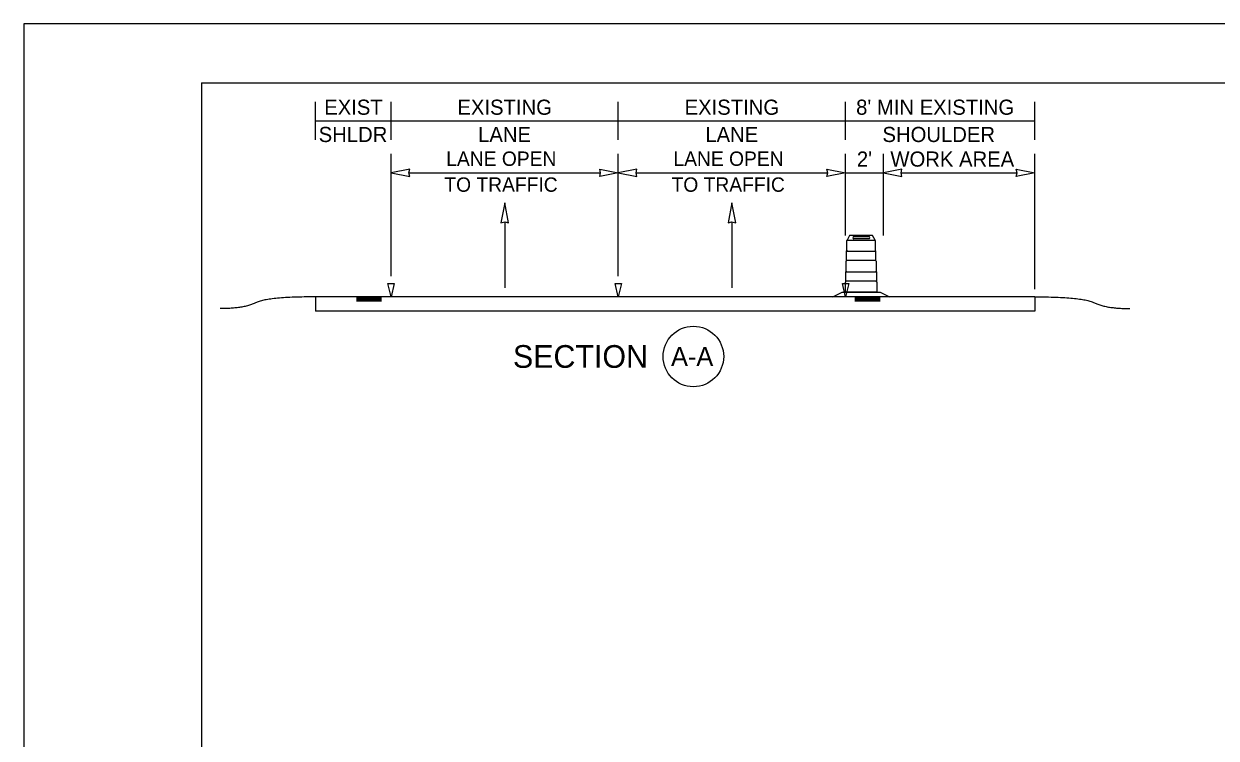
# Model space of a CAD drawing. Extents: x 99999.1 to 100055.7, y 99995 to 100013.2.
# Drawn here: x 99999.06 to 100005.36, y 100006.91 to 100010.69 of the extents above; entities that cross this region are included whole.
import ezdxf

# ---------------------------------------------------------------- set-up
doc = ezdxf.new("R2010")
doc.units = 0
for name, color, linetype in [('SH_GI_PlotLimits', 7, 'Continuous'), ('SH_GI_SheetBorder', 7, 'Continuous'), ('SH_TI_WZSectionCut', 7, 'Continuous'), ('TR_WZ_ArrowLeftStrRightTurn', 7, 'Continuous'), ('TR_WZ_TrafficSafetyDrumElev', 7, 'Continuous')]:
    doc.layers.add(name, color=color, linetype=linetype)

msp = doc.modelspace()

# ---------------------------------------------------------------- linework, layer by layer
at = {"layer": 'SH_GI_PlotLimits'}
msp.add_lwpolyline([(99999.0625, 99999.6875), (100016.0625, 99999.6875), (100016.0625, 100010.6875), (99999.0625, 100010.6875)], close=True, dxfattribs=at)
at = {"layer": 'SH_GI_SheetBorder'}
for q in [(100000, 100000), (100015.75, 100010.375)]:
    msp.add_line((100000, 100010.375), q, dxfattribs=at)
at = {"layer": 'SH_TI_WZSectionCut'}
for p, q in [((100000.6021, 100010.075), (100000.6021, 100010.275)), ((100001.0021, 100010.075), (100001.0021, 100010.275)), ((100002.2021, 100010.075), (100002.2021, 100010.275)), ((100003.4021, 100010.075), (100003.4021, 100010.275)), ((100004.4021, 100010.075), (100004.4021, 100010.275)), ((100000.6021, 100010.175), (100001.0021, 100010.175)), ((100001.0021, 100010.175), (100002.2021, 100010.175)), ((100002.2021, 100010.175), (100003.4021, 100010.175)), ((100003.4021, 100010.175), (100004.4021, 100010.175)), ((100001.0021, 100009.3547), (100001.0021, 100010.001)), ((100002.2021, 100009.3547), (100002.2021, 100010.001)), ((100003.4021, 100009.57), (100003.4021, 100010.001)), ((100003.6021, 100009.57), (100003.6021, 100010.001)), ((100004.4021, 100009.2849), (100004.4021, 100010.001)), ((100001.0958, 100009.901), (100002.1084, 100009.901)), ((100002.2958, 100009.901), (100003.3084, 100009.901)), ((100003.4021, 100009.901), (100003.6021, 100009.901)), ((100003.6958, 100009.901), (100004.3084, 100009.901)), ((100000.6021, 100009.2449), (100000.6021, 100009.1699)), ((100004.4021, 100009.2449), (100000.6021, 100009.2449)), ((100000.8191, 100009.2397), (100000.9521, 100009.2397)), ((100000.8191, 100009.2341), (100000.9521, 100009.2341)), ((100003.5851, 100009.2393), (100003.4521, 100009.2393)), ((100003.5851, 100009.2337), (100003.4521, 100009.2337)), ((100004.4021, 100009.2449), (100004.4021, 100009.1699)), ((100004.4021, 100009.1699), (100000.6021, 100009.1699)), ((100000.8191, 100009.2284), (100000.9521, 100009.2284)), ((100000.8191, 100009.2232), (100000.9521, 100009.2232)), ((100003.5851, 100009.228), (100003.4521, 100009.228)), ((100003.5851, 100009.2228), (100003.4521, 100009.2228))]:
    msp.add_line(p, q, dxfattribs=at)
for points in [[(100001.0021, 100009.901), (100001.1004, 100009.8817), (100001.0958, 100009.901), (100001.1004, 100009.9203)], [(100002.2021, 100009.901), (100002.1038, 100009.8817), (100002.1084, 100009.901), (100002.1038, 100009.9203)], [(100002.2021, 100009.901), (100002.3004, 100009.8817), (100002.2958, 100009.901), (100002.3004, 100009.9203)], [(100003.4021, 100009.901), (100003.3038, 100009.8817), (100003.3084, 100009.901), (100003.3038, 100009.9203)], [(100003.6021, 100009.901), (100003.7004, 100009.8817), (100003.6958, 100009.901), (100003.7004, 100009.9203)], [(100004.4021, 100009.901), (100004.3038, 100009.8817), (100004.3084, 100009.901), (100004.3038, 100009.9203)], [(100000.9854, 100009.3147), (100001.0188, 100009.3147), (100001.0021, 100009.2449)], [(100002.1854, 100009.3147), (100002.2188, 100009.3147), (100002.2021, 100009.2449)], [(100003.3854, 100009.3147), (100003.4188, 100009.3147), (100003.4021, 100009.2449)]]:
    msp.add_lwpolyline(points, close=True, dxfattribs=at)
msp.add_circle((100002.5987, 100008.93), 0.16, dxfattribs=at)
for points in [[(100000.6021, 100009.2449), (100000.3509, 100009.2449), (100000.2255, 100009.1828), (100000.1, 100009.1828)], [(100004.4021, 100009.2449), (100004.6533, 100009.2451), (100004.7788, 100009.183), (100004.9043, 100009.1831)]]:
    msp.add_open_spline(points, degree=2, dxfattribs=at)
at = {"layer": 'TR_WZ_ArrowLeftStrRightTurn'}
for p, q in [((100001.6021, 100009.6418), (100001.6021, 100009.292)), ((100002.8021, 100009.6418), (100002.8021, 100009.292))]:
    msp.add_line(p, q, dxfattribs=at)
for points in [[(100001.6021, 100009.742), (100001.5815, 100009.6369), (100001.6021, 100009.6418), (100001.6227, 100009.6369)], [(100002.8021, 100009.742), (100002.7815, 100009.6369), (100002.8021, 100009.6418), (100002.8227, 100009.6369)]]:
    msp.add_lwpolyline(points, close=True, dxfattribs=at)
at = {"layer": 'TR_WZ_TrafficSafetyDrumElev'}
for p, q in [((100003.4105, 100009.545), (100003.5585, 100009.545)), ((100003.4105, 100009.545), (100003.5585, 100009.545)), ((100003.445, 100009.564), (100003.5267, 100009.564)), ((100003.5267, 100009.551), (100003.445, 100009.551)), ((100003.4076, 100009.4871), (100003.5613, 100009.4871)), ((100003.4076, 100009.4372), (100003.4076, 100009.4871)), ((100003.5613, 100009.4871), (100003.5613, 100009.4372)), ((100003.5613, 100009.4372), (100003.4076, 100009.4372)), ((100003.404, 100009.377), (100003.565, 100009.377)), ((100003.404, 100009.3271), (100003.404, 100009.377)), ((100003.565, 100009.377), (100003.565, 100009.3271)), ((100003.565, 100009.3271), (100003.404, 100009.3271))]:
    msp.add_line(p, q, dxfattribs=at)
for points in [[(100003.5585, 100009.545), (100003.5454, 100009.57), (100003.4236, 100009.57), (100003.4105, 100009.545)], [(100003.3345, 100009.245), (100003.3847, 100009.27), (100003.5843, 100009.27), (100003.6345, 100009.245)]]:
    msp.add_lwpolyline(points, close=True, dxfattribs=at)
for points in [[(100003.4076, 100009.4365), (100003.4076, 100009.4878)], [(100003.4076, 100009.4365), (100003.4076, 100009.4878)], [(100003.4095, 100009.4915), (100003.4095, 100009.543)], [(100003.4095, 100009.4915), (100003.4095, 100009.543)], [(100003.5595, 100009.543), (100003.5595, 100009.4915)], [(100003.5595, 100009.543), (100003.5595, 100009.4915)], [(100003.5613, 100009.4878), (100003.5613, 100009.4365)], [(100003.5613, 100009.4878), (100003.5613, 100009.4365)], [(100003.4058, 100009.3814), (100003.4058, 100009.4327)], [(100003.4058, 100009.3814), (100003.4058, 100009.4327)], [(100003.5632, 100009.4327), (100003.5632, 100009.3814)], [(100003.5632, 100009.4327), (100003.5632, 100009.3814)], [(100003.404, 100009.3264), (100003.404, 100009.3777)], [(100003.404, 100009.3264), (100003.404, 100009.3777)], [(100003.565, 100009.3777), (100003.565, 100009.3264)], [(100003.565, 100009.3777), (100003.565, 100009.3264)], [(100003.5669, 100009.3226), (100003.5669, 100009.27), (100003.4021, 100009.27), (100003.4021, 100009.3226)], [(100003.5669, 100009.3226), (100003.5669, 100009.27), (100003.4021, 100009.27), (100003.4021, 100009.3226)]]:
    msp.add_lwpolyline(points, dxfattribs=at)
for centre, major_axis, ratio, start_param, end_param in [((100003.4107, 100009.5426), (0, 0.00249), 0.493438, 0.177149, 1.393647), ((100003.4107, 100009.5426), (0, 0.00249), 0.493438, 0.177149, 1.393647), ((100003.445, 100009.5575), (0, 0.0065), 0.570305, 0, 3.141593), ((100003.5267, 100009.5575), (0, 0.0065), 0.570305, 3.141593, 6.283185), ((100003.5583, 100009.5426), (0, 0.00249), 0.493438, 4.889538, 6.106036), ((100003.5583, 100009.5426), (0, 0.00249), 0.493438, 4.889538, 6.106036), ((100003.4111, 100009.4846), (0, 0.00758), 0.493438, 0.4288, 1.141997), ((100003.4111, 100009.4846), (0, 0.00758), 0.493438, 0.4288, 1.141997), ((100003.5579, 100009.4846), (0, 0.00758), 0.493438, 5.141189, 5.854386), ((100003.5579, 100009.4846), (0, 0.00758), 0.493438, 5.141189, 5.854386), ((100003.4092, 100009.4296), (0, 0.00758), 0.493438, 0.4288, 1.141997), ((100003.4092, 100009.4296), (0, 0.00758), 0.493438, 0.4288, 1.141997), ((100003.5598, 100009.4296), (0, 0.00758), 0.493438, 5.141189, 5.854386), ((100003.5598, 100009.4296), (0, 0.00758), 0.493438, 5.141189, 5.854386), ((100003.4074, 100009.3745), (0, 0.00758), 0.493438, 0.4288, 1.141997), ((100003.4074, 100009.3745), (0, 0.00758), 0.493438, 0.4288, 1.141997), ((100003.5616, 100009.3745), (0, 0.00758), 0.493438, 5.141189, 5.854386), ((100003.5616, 100009.3745), (0, 0.00758), 0.493438, 5.141189, 5.854386), ((100003.4055, 100009.3195), (0, 0.00758), 0.493438, 0.4288, 1.141997), ((100003.4055, 100009.3195), (0, 0.00758), 0.493438, 0.4288, 1.141997), ((100003.5635, 100009.3195), (0, 0.00758), 0.493438, 5.141189, 5.854386), ((100003.5635, 100009.3195), (0, 0.00758), 0.493438, 5.141189, 5.854386)]:
    msp.add_ellipse(centre, major_axis=major_axis, ratio=ratio, start_param=start_param, end_param=end_param, dxfattribs=at)

# ---------------------------------------------------------------- texts
at = {"layer": 'SH_TI_WZSectionCut'}
for s, height, p in [('EXIST', 0.08, (100000.6489, 100010.207)), ('EXISTING', 0.08, (100001.3523, 100010.207)), ('EXISTING', 0.08, (100002.5523, 100010.207)), ("8' MIN EXISTING", 0.08, (100003.4582, 100010.207)), ('SHLDR', 0.08, (100000.6196, 100010.063)), ('LANE', 0.08, (100001.4617, 100010.063)), ('LANE', 0.08, (100002.6617, 100010.063)), ('SHOULDER', 0.08, (100003.5973, 100010.063)), ('SECTION', 0.12, (100001.6456, 100008.87)), ('A-A', 0.1, (100002.4808, 100008.88))]:
    msp.add_text(s, height=height, rotation=360, dxfattribs=at).set_placement(p)
for s, height, p in [('LANE OPEN', 0.076, (100001.2934, 100009.937)), ('LANE OPEN', 0.076, (100002.4934, 100009.937)), ("2'", 0.08, (100003.4621, 100009.933)), ('WORK AREA', 0.08, (100003.6392, 100009.933)), ('TO TRAFFIC', 0.076, (100001.2834, 100009.8002)), ('TO TRAFFIC', 0.076, (100002.4834, 100009.8002))]:
    msp.add_text(s, height=height, dxfattribs=at).set_placement(p)

doc.saveas('drawing.dxf')
